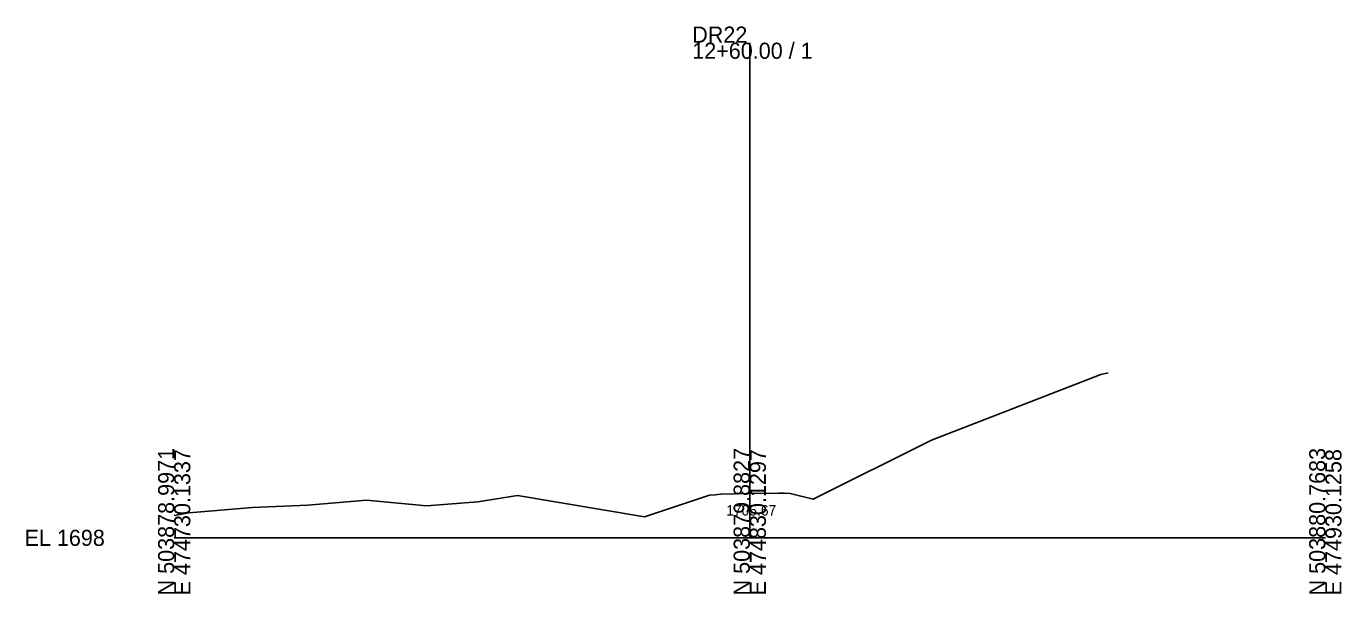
# Model space of a CAD drawing. Extents: x -26 to 1203, y -10 to 9633.
# Drawn here: x -25.7 to 202.8, y 6490.3 to 6588.8 of the extents above; entities that cross this region are included whole.
import ezdxf

# ---------------------------------------------------------------- set-up
doc = ezdxf.new("R2010")
doc.units = 0
for name, color, linetype in [('Exist Cross Section Cell', 7, 'Continuous'), ('Exist XS Center Line Elevation Label', 7, 'Continuous'), ('Exist XS Ground Line', 7, 'Continuous'), ('Scratch_Level_5', 7, 'Continuous')]:
    doc.layers.add(name, color=color, linetype=linetype)

msp = doc.modelspace()

# ---------------------------------------------------------------- linework, layer by layer
at = {"layer": 'Exist Cross Section Cell'}
for p, q in [((100, 6500), (100, 6585.95)), ((0, 6500), (100, 6500)), ((100, 6500), (200, 6500))]:
    msp.add_line(p, q, dxfattribs=at)
at = {"layer": 'Exist XS Ground Line'}
msp.add_lwpolyline([(0, 6503.85), (2.56, 6504.34), (13.59, 6505.24), (23.24, 6505.68), (33.39, 6506.55), (43.81, 6505.54), (52.78, 6506.23), (59.65, 6507.37), (81.7, 6503.64), (93, 6507.41), (93.98, 6507.49), (95, 6507.57), (100, 6507.67), (105, 6507.77), (106.02, 6507.73), (107, 6507.69), (111, 6506.69), (131.55, 6516.96), (161, 6528.34), (162.25, 6528.65)], dxfattribs=at)
at = {"layer": 'Scratch_Level_5'}
msp.add_lwpolyline([(0, 6503.85), (2.56, 6504.34), (13.59, 6505.24), (23.24, 6505.68), (33.39, 6506.55), (43.81, 6505.54), (52.78, 6506.23), (59.65, 6507.37), (81.7, 6503.64), (93, 6507.41), (93.98, 6507.49), (95, 6507.57), (100, 6507.67), (105, 6507.77), (106.02, 6507.73), (107, 6507.69), (111, 6506.69), (131.55, 6516.96), (161, 6528.34), (162.25, 6528.65)], dxfattribs=at)

# ---------------------------------------------------------------- texts
at = {"layer": 'Exist Cross Section Cell'}
for s, p in [('DR22', (90, 6585.95)), ('12+60.00 / 1', (90, 6583.15)), ('EL 1698', (-26, 6498.6))]:
    msp.add_text(s, height=2.8, dxfattribs=at).set_placement(p)
for s, p in [('N 503878.9971', (0, 6490)), ('E 474730.1337', (2.8, 6490)), ('N 503879.8827', (100, 6490)), ('E 474830.1297', (102.8, 6490)), ('N 503880.7683', (200, 6490)), ('E 474930.1258', (202.8, 6490))]:
    msp.add_text(s, height=2.8, rotation=90, dxfattribs=at).set_placement(p)
at = {"layer": 'Exist XS Center Line Elevation Label'}
msp.add_text('1705.67', height=1.8, dxfattribs=at).set_placement((95.9, 6503.87))

doc.saveas('drawing.dxf')
